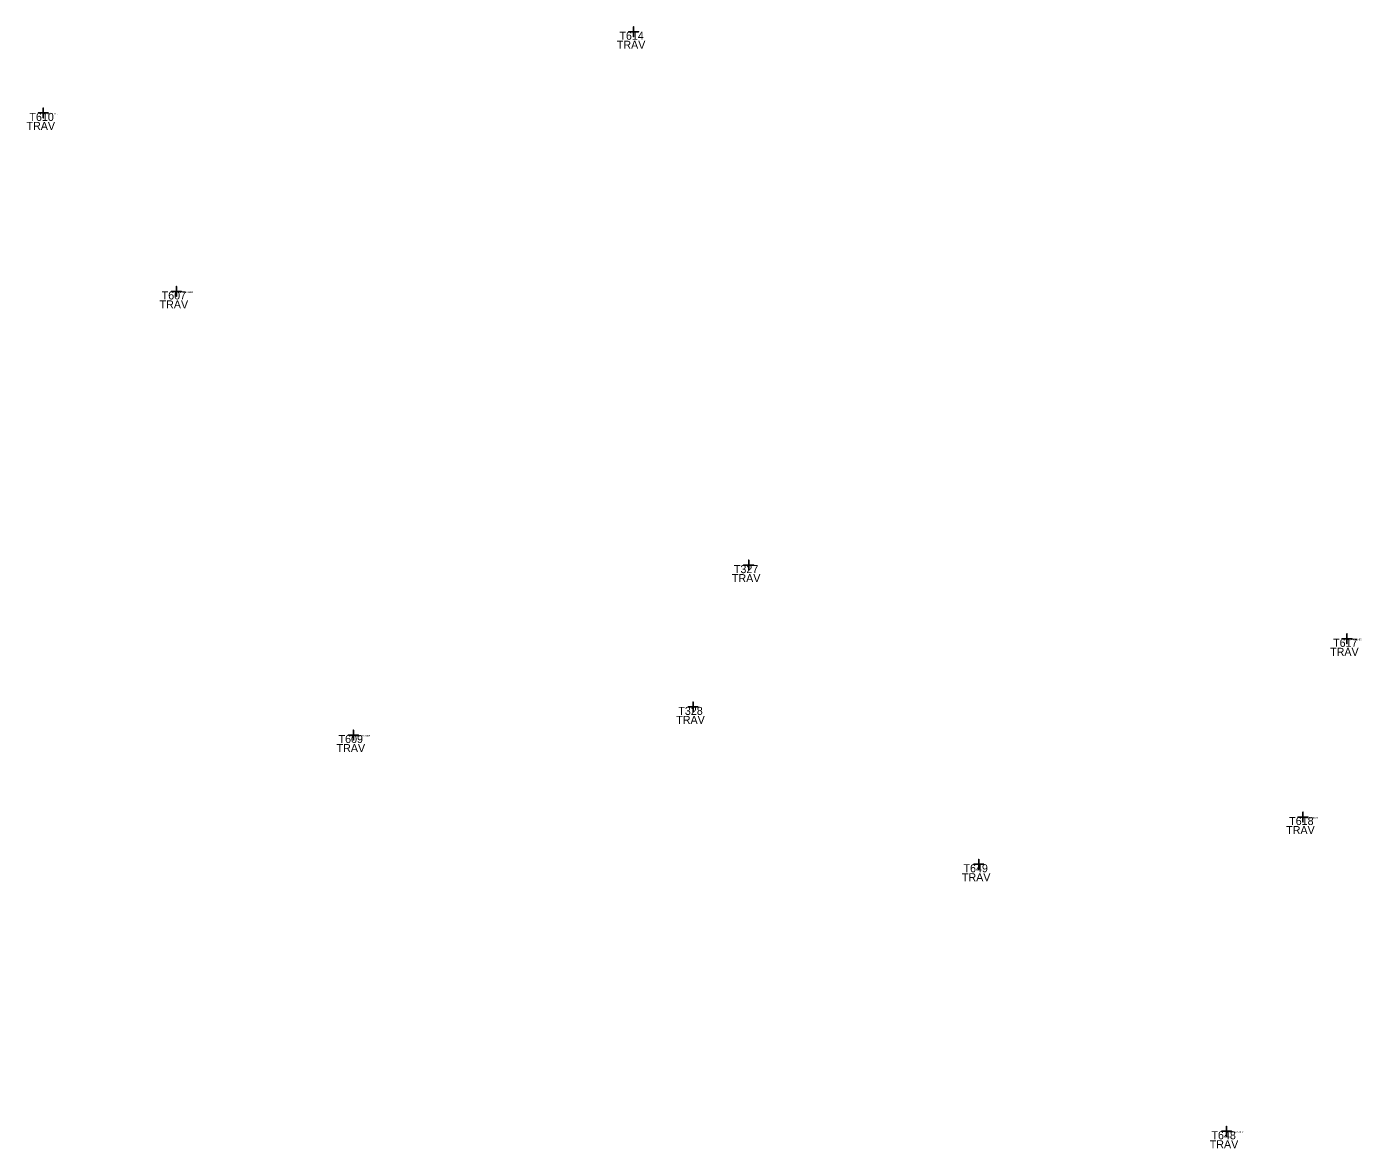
# Model space of a CAD drawing. Extents: x 2342247 to 2353588, y 365809 to 372747.
# Drawn here: x 2344876 to 2346209, y 368737 to 369857 of the extents above; entities that cross this region are included whole.
import ezdxf

# ---------------------------------------------------------------- set-up
doc = ezdxf.new("R2010")
doc.units = 0
for name, color, linetype in [('Level 63', 7, 'Continuous'), ('SV_Control_CP_Code', 7, 'Continuous'), ('SV_Control_CP_Name', 7, 'Continuous'), ('SV_Control_CP_Shot', 7, 'Continuous')]:
    doc.layers.add(name, color=color, linetype=linetype)

msp = doc.modelspace()

# ---------------------------------------------------------------- linework, layer by layer
at = {"layer": 'SV_Control_CP_Shot'}
for points in [[(2345482.2, 369852), (2345482.2, 369857), (2345482.2, 369852), (2345477.2, 369852), (2345482.2, 369852), (2345482.2, 369847), (2345482.2, 369852), (2345487.2, 369852)], [(2344892.2, 369770.9), (2344892.2, 369775.9), (2344892.2, 369770.9), (2344887.2, 369770.9), (2344892.2, 369770.9), (2344892.2, 369765.9), (2344892.2, 369770.9), (2344897.2, 369770.9)], [(2345025.3, 369592.6), (2345025.3, 369597.6), (2345025.3, 369592.6), (2345020.3, 369592.6), (2345025.3, 369592.6), (2345025.3, 369587.6), (2345025.3, 369592.6), (2345030.3, 369592.6)], [(2345597.2, 369319.2), (2345597.2, 369324.2), (2345597.2, 369319.2), (2345592.2, 369319.2), (2345597.2, 369319.2), (2345597.2, 369314.2), (2345597.2, 369319.2), (2345602.2, 369319.2)], [(2346195.1, 369245.6), (2346195.1, 369250.6), (2346195.1, 369245.6), (2346190.1, 369245.6), (2346195.1, 369245.6), (2346195.1, 369240.6), (2346195.1, 369245.6), (2346200.1, 369245.6)], [(2345541.6, 369177.6), (2345541.6, 369182.6), (2345541.6, 369177.6), (2345536.6, 369177.6), (2345541.6, 369177.6), (2345541.6, 369172.6), (2345541.6, 369177.6), (2345546.6, 369177.6)], [(2345202.1, 369149.5), (2345202.1, 369154.5), (2345202.1, 369149.5), (2345197.1, 369149.5), (2345202.1, 369149.5), (2345202.1, 369144.5), (2345202.1, 369149.5), (2345207.1, 369149.5)], [(2346151.2, 369067.6), (2346151.2, 369072.6), (2346151.2, 369067.6), (2346146.2, 369067.6), (2346151.2, 369067.6), (2346151.2, 369062.6), (2346151.2, 369067.6), (2346156.2, 369067.6)], [(2345827.1, 369020.4), (2345827.1, 369025.4), (2345827.1, 369020.4), (2345822.1, 369020.4), (2345827.1, 369020.4), (2345827.1, 369015.4), (2345827.1, 369020.4), (2345832.1, 369020.4)], [(2346074.8, 368753.7), (2346074.8, 368758.7), (2346074.8, 368753.7), (2346069.8, 368753.7), (2346074.8, 368753.7), (2346074.8, 368748.7), (2346074.8, 368753.7), (2346079.8, 368753.7)]]:
    msp.add_lwpolyline(points, close=True, dxfattribs=at)

# ---------------------------------------------------------------- texts
at = {"layer": 'Level 63'}
for s, p in [('PK W/WASHER', (2344892.2, 369769.4)), ('NAIL W/WASHER', (2345025.3, 369591.1)), ('PK W/WASHER', (2346195.1, 369244.1)), ('NAIL W/WASHER', (2345202.1, 369148)), ('PK W/WASHER', (2346151.2, 369066.1)), ('NAIL W/WASHER', (2346074.8, 368752.2))]:
    msp.add_text(s, height=1.5, dxfattribs=at).set_placement(p)
at = {"layer": 'SV_Control_CP_Code'}
for p in [(2345465.4, 369835), (2344875.4, 369753.9), (2345008.4, 369575.6), (2345580.4, 369302.2), (2346178.3, 369228.6), (2345524.8, 369160.6), (2345185.3, 369132.5), (2346134.4, 369050.6), (2345810.3, 369003.4), (2346058, 368736.7)]:
    msp.add_text('TRAV', height=8, dxfattribs=at).set_placement(p)
at = {"layer": 'SV_Control_CP_Name'}
for s, p in [('T614', (2345468, 369844)), ('T610', (2344878.3, 369762.9)), ('T607', (2345010.5, 369584.6)), ('T327', (2345582.4, 369311.2)), ('T617', (2346181.3, 369237.6)), ('T328', (2345526.9, 369169.6)), ('T609', (2345187.3, 369141.5)), ('T618', (2346137.4, 369059.6)), ('T649', (2345811.9, 369012.4)), ('T648', (2346059.7, 368745.7))]:
    msp.add_text(s, height=8, dxfattribs=at).set_placement(p)

doc.saveas('drawing.dxf')
